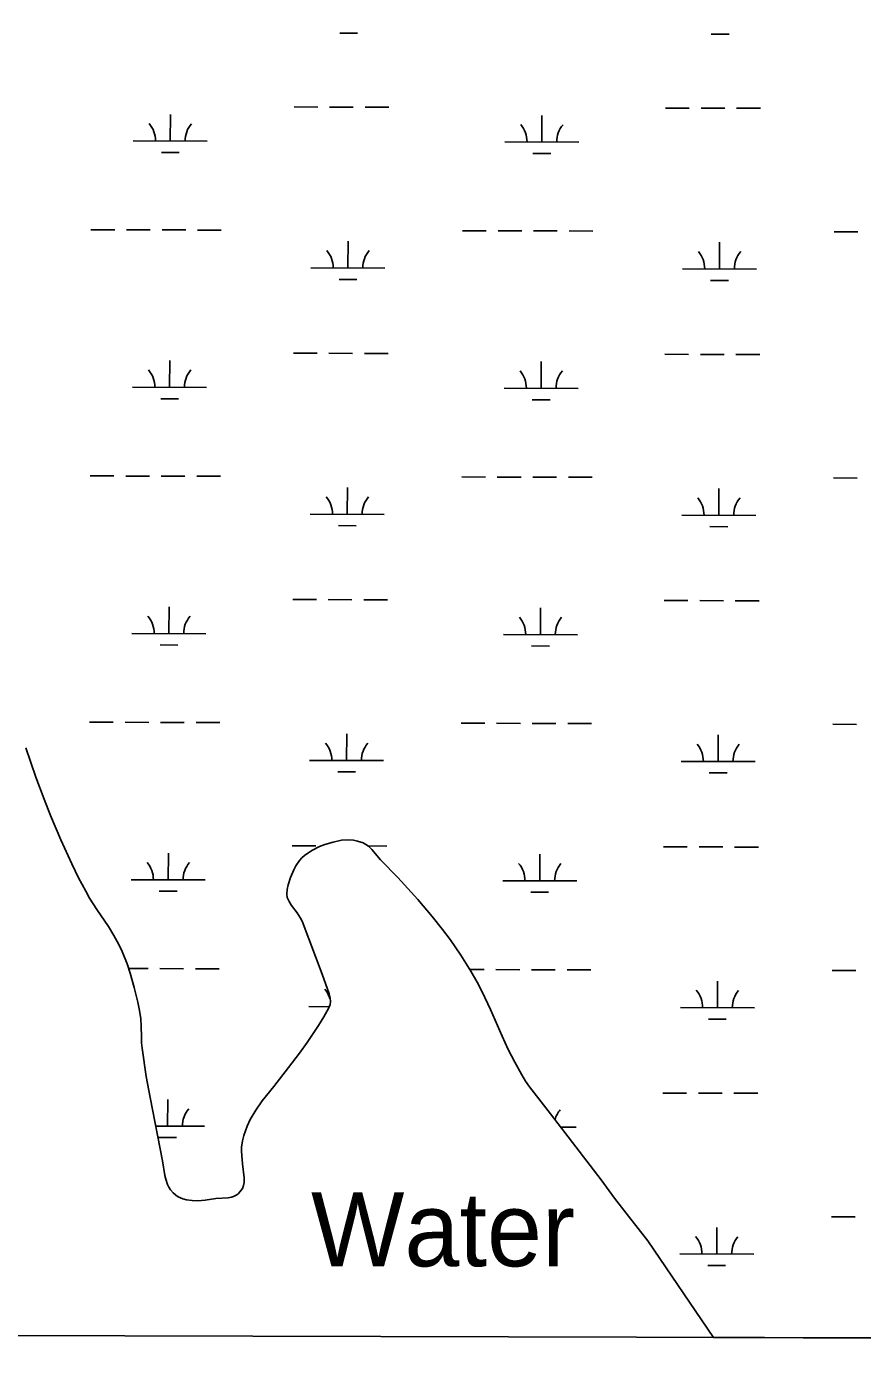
# Model space of a CAD drawing. Extents: x 3161615 to 3199515, y 867541 to 892976.
# Drawn here: x 3184624 to 3185752, y 872921 to 874724 of the extents above; entities that cross this region are included whole.
import ezdxf

# ---------------------------------------------------------------- set-up
doc = ezdxf.new("R2010")
doc.units = 0
for name, color, linetype in [('V-GRID-FRAM', 7, 'Continuous'), ('V-RIVR-IDEN', 7, 'Continuous'), ('V-SITE-VEGE', 7, 'Continuous'), ('V-TOPO-SHOR', 7, 'Continuous'), ('V-WETL-SWMP', 7, 'Continuous')]:
    doc.layers.add(name, color=color, linetype=linetype)

msp = doc.modelspace()

# ---------------------------------------------------------------- linework, layer by layer
at = {"layer": 'V-GRID-FRAM'}
msp.add_lwpolyline([(3165877.4, 891195.5), (3197229, 891108.8), (3197186.7, 872920.9), (3165819.2, 873007.6), (3165877.4, 891195.5)], dxfattribs=at)
at = {"layer": 'V-SITE-VEGE'}
for p, q in [((3184622.6, 873749.8), (3184636.1, 873709.8)), ((3184636.1, 873709.8), (3184647.2, 873680.2)), ((3184647.2, 873680.2), (3184655.9, 873658.1)), ((3184655.9, 873658.1), (3184669.8, 873625.3)), ((3184669.8, 873625.3), (3184684.6, 873592.8)), ((3185009.9, 873611.5), (3185019.2, 873616.2)), ((3185019.2, 873616.2), (3185026.4, 873619)), ((3185026.4, 873619), (3185037.5, 873622.3)), ((3185037.5, 873622.3), (3185048.9, 873624.7)), ((3185048.9, 873624.7), (3185056.9, 873625.5)), ((3185056.9, 873625.5), (3185065, 873624.9)), ((3185065, 873624.9), (3185070.4, 873623.7)), ((3185070.4, 873623.7), (3185078.4, 873621.2)), ((3185078.4, 873621.2), (3185082, 873619.2)), ((3185082, 873619.2), (3185085.3, 873616.6)), ((3185085.3, 873616.6), (3185089.7, 873612.1)), ((3184987.1, 873590.1), (3184992.2, 873597.4)), ((3184992.2, 873597.4), (3184995.3, 873600.8)), ((3184995.3, 873600.8), (3184998.8, 873604)), ((3184998.8, 873604), (3185004.7, 873608.3)), ((3185004.7, 873608.3), (3185009.9, 873611.5)), ((3185089.7, 873612.1), (3185101.5, 873598.3)), ((3185101.5, 873598.3), (3185124.8, 873574.6)), ((3184684.6, 873592.8), (3184693.7, 873574.1)), ((3184980.1, 873574.6), (3184984.3, 873584.7)), ((3184984.3, 873584.7), (3184987.1, 873590.1)), ((3184693.7, 873574.1), (3184703.4, 873555.8)), ((3184975.5, 873558), (3184977, 873564.4)), ((3184977, 873564.4), (3184980.1, 873574.6)), ((3185124.8, 873574.6), (3185151.9, 873544.8)), ((3184703.4, 873555.8), (3184708.6, 873546.6)), ((3184708.6, 873546.6), (3184718.6, 873531.1)), ((3184975, 873551.7), (3184975.5, 873558)), ((3184975.6, 873547.6), (3184975, 873551.7)), ((3184978, 873542), (3184975.6, 873547.6)), ((3184981.2, 873536.7), (3184978, 873542)), ((3185151.9, 873544.8), (3185171.3, 873521.8)), ((3184718.6, 873531.1), (3184734.2, 873508.1)), ((3184989, 873526.6), (3184981.2, 873536.7)), ((3184993.6, 873519.6), (3184989, 873526.6)), ((3184734.2, 873508.1), (3184741.5, 873496.3)), ((3184995.6, 873515.3), (3184993.6, 873519.6)), ((3185022.9, 873443.7), (3184995.6, 873515.3)), ((3185171.3, 873521.8), (3185185.4, 873504.1)), ((3184741.5, 873496.3), (3184748.2, 873484)), ((3185185.4, 873504.1), (3185195.5, 873490.5)), ((3185195.5, 873490.5), (3185210, 873469.6)), ((3184748.2, 873484), (3184752.6, 873474.6)), ((3184752.6, 873474.6), (3184759.2, 873458)), ((3184759.2, 873458), (3184763.4, 873445.2)), ((3185210, 873469.6), (3185223.7, 873448.1)), ((3184763.4, 873445.2), (3184768.9, 873425.8)), ((3185032.4, 873417.5), (3185022.9, 873443.7)), ((3185223.7, 873448.1), (3185232.1, 873433.1)), ((3184768.9, 873425.8), (3184773.7, 873406.2)), ((3185033.8, 873412.1), (3185032.4, 873417.5)), ((3185232.1, 873433.1), (3185238.9, 873419.8)), ((3185238.9, 873419.8), (3185250, 873396)), ((3184773.7, 873406.2), (3184776.1, 873394.9)), ((3185025, 873386.1), (3185031.9, 873398.2)), ((3185031.9, 873398.2), (3185033.6, 873402.8)), ((3185033.6, 873402.8), (3185034.1, 873406.5)), ((3185034.1, 873406.5), (3185033.8, 873412.1)), ((3184776.1, 873394.9), (3184777.8, 873383.5)), ((3184777.8, 873383.5), (3184778.5, 873373.6)), ((3185017.8, 873374.4), (3185025, 873386.1)), ((3185250, 873396), (3185265.9, 873360)), ((3184778.5, 873373.6), (3184778.6, 873358.6)), ((3185002.6, 873351.7), (3185017.8, 873374.4)), ((3184778.6, 873358.6), (3184778.9, 873351.2)), ((3184778.9, 873351.2), (3184779.5, 873343.7)), ((3184779.5, 873343.7), (3184785.2, 873305.6)), ((3184992, 873337), (3185002.6, 873351.7)), ((3185265.9, 873360), (3185274.2, 873342.2)), ((3184977.5, 873317.7), (3184992, 873337)), ((3185274.2, 873342.2), (3185283.2, 873324.8)), ((3184957.7, 873292.2), (3184977.5, 873317.7)), ((3185283.2, 873324.8), (3185292.4, 873307.8)), ((3185292.4, 873307.8), (3185297.3, 873299.5)), ((3184785.2, 873305.6), (3184790.3, 873277.1)), ((3184941.6, 873272.7), (3184957.7, 873292.2)), ((3185297.3, 873299.5), (3185302.8, 873291.5)), ((3185302.8, 873291.5), (3185331.3, 873255.2)), ((3184790.3, 873277.1), (3184807.2, 873191.9)), ((3184933.1, 873260.3), (3184941.6, 873272.7)), ((3184925.7, 873247.3), (3184933.1, 873260.3)), ((3185331.3, 873255.2), (3185399.5, 873166.2)), ((3184917.2, 873225.9), (3184921.5, 873238.3)), ((3184921.5, 873238.3), (3184925.7, 873247.3)), ((3184913.9, 873210.2), (3184915.3, 873218.7)), ((3184915.3, 873218.7), (3184917.2, 873225.9)), ((3184913.7, 873204.6), (3184913.9, 873210.2)), ((3184915.2, 873187.6), (3184913.7, 873204.6)), ((3184807.2, 873191.9), (3184810.3, 873172)), ((3184917.5, 873168.5), (3184915.2, 873187.6)), ((3184810.3, 873172), (3184811.5, 873167)), ((3184811.5, 873167), (3184814, 873159.7)), ((3184917.4, 873162.2), (3184917.5, 873168.5)), ((3185399.5, 873166.2), (3185417.8, 873141.4)), ((3184814, 873159.7), (3184815.8, 873156.1)), ((3184815.8, 873156.1), (3184818, 873152.5)), ((3184818, 873152.5), (3184821.5, 873148.3)), ((3184821.5, 873148.3), (3184824.9, 873145.2)), ((3184824.9, 873145.2), (3184828.3, 873143.1)), ((3184903.2, 873143.5), (3184907.6, 873145.9)), ((3184907.6, 873145.9), (3184909.7, 873147.6)), ((3184909.7, 873147.6), (3184911.8, 873149.7)), ((3184911.8, 873149.7), (3184915, 873154.4)), ((3184915, 873154.4), (3184916.7, 873158.5)), ((3184916.7, 873158.5), (3184917.4, 873162.2)), ((3184828.3, 873143.1), (3184834.6, 873140.3)), ((3184834.6, 873140.3), (3184839.6, 873138.9)), ((3184839.6, 873138.9), (3184847.3, 873137.9)), ((3184847.3, 873137.9), (3184855, 873137.7)), ((3184855, 873137.7), (3184859.8, 873138)), ((3184859.8, 873138), (3184864.6, 873138.5)), ((3184864.6, 873138.5), (3184879, 873140.7)), ((3184879, 873140.7), (3184896, 873141.8)), ((3184896, 873141.8), (3184900.1, 873142.5)), ((3184900.1, 873142.5), (3184903.2, 873143.5)), ((3185417.8, 873141.4), (3185436.4, 873116.8)), ((3185436.4, 873116.8), (3185462.8, 873083.4)), ((3185462.8, 873083.4), (3185551.6, 872953)), ((3185551.6, 872953), (3188886.4, 872943.8))]:
    msp.add_line(p, q, dxfattribs=at)
at = {"layer": 'V-TOPO-SHOR'}
for points in [[(3184622.6, 873749.8), (3184636.1, 873709.8), (3184647.2, 873680.2), (3184655.9, 873658.1), (3184669.8, 873625.3), (3184684.6, 873592.8), (3184693.7, 873574.1), (3184703.4, 873555.8), (3184708.6, 873546.6), (3184718.6, 873531.1), (3184734.2, 873508.1), (3184741.5, 873496.3), (3184748.2, 873484), (3184752.6, 873474.6), (3184759.2, 873458), (3184763.4, 873445.2), (3184768.9, 873425.8), (3184773.7, 873406.2), (3184776.1, 873394.9), (3184777.8, 873383.5), (3184778.5, 873373.6), (3184778.6, 873358.6), (3184778.9, 873351.2), (3184779.5, 873343.7), (3184785.2, 873305.6), (3184790.3, 873277.1), (3184807.2, 873191.9), (3184810.3, 873172), (3184811.5, 873167), (3184814, 873159.7), (3184815.8, 873156.1), (3184818, 873152.5), (3184821.5, 873148.3), (3184824.9, 873145.2), (3184828.3, 873143.1), (3184834.6, 873140.3), (3184839.6, 873138.9), (3184847.3, 873137.9), (3184855, 873137.7), (3184859.8, 873138), (3184864.6, 873138.5), (3184879, 873140.7), (3184896, 873141.8), (3184900.1, 873142.5), (3184903.2, 873143.5), (3184907.6, 873145.9), (3184909.7, 873147.6), (3184911.8, 873149.7), (3184915, 873154.4), (3184916.7, 873158.5), (3184917.4, 873162.2)], [(3184917.4, 873162.2), (3184917.5, 873168.5), (3184915.2, 873187.6), (3184914.2, 873198.9), (3184913.7, 873204.6), (3184913.9, 873210.2), (3184915.3, 873218.7), (3184917.2, 873225.9), (3184921.5, 873238.3), (3184925.7, 873247.3), (3184933.1, 873260.3), (3184941.6, 873272.7), (3184957.7, 873292.2), (3184977.5, 873317.7), (3184992, 873337), (3185002.6, 873351.7), (3185017.8, 873374.4), (3185025, 873386.1), (3185031.9, 873398.2), (3185033.6, 873402.8), (3185034.1, 873406.5), (3185033.8, 873412.1), (3185032.4, 873417.5), (3185022.9, 873443.7), (3184995.6, 873515.3), (3184993.6, 873519.6), (3184989, 873526.6), (3184981.2, 873536.7), (3184978, 873542), (3184975.6, 873547.6), (3184975, 873551.7), (3184975.5, 873558), (3184977, 873564.4), (3184980.1, 873574.6), (3184984.3, 873584.7), (3184987.1, 873590.1), (3184992.2, 873597.4), (3184995.3, 873600.8), (3184998.8, 873604), (3185004.7, 873608.3), (3185009.9, 873611.5), (3185019.2, 873616.2), (3185026.4, 873619), (3185037.5, 873622.3), (3185048.9, 873624.7), (3185056.9, 873625.5), (3185065, 873624.9), (3185070.4, 873623.7), (3185078.4, 873621.2), (3185082, 873619.2), (3185085.3, 873616.6), (3185089.7, 873612.1), (3185101.5, 873598.3), (3185124.8, 873574.6), (3185151.9, 873544.8), (3185171.3, 873521.8), (3185185.4, 873504.1), (3185195.5, 873490.5), (3185210, 873469.6), (3185223.7, 873448.1), (3185232.1, 873433.1), (3185238.9, 873419.8), (3185250, 873396), (3185265.9, 873360), (3185274.2, 873342.2), (3185283.2, 873324.8), (3185292.4, 873307.8), (3185297.3, 873299.5), (3185302.8, 873291.5), (3185331.3, 873255.2), (3185399.5, 873166.2), (3185417.8, 873141.4), (3185436.4, 873116.8), (3185462.8, 873083.4)], [(3185462.8, 873083.4), (3185551.6, 872953)]]:
    msp.add_lwpolyline(points, dxfattribs=at)
at = {"layer": 'V-WETL-SWMP'}
for p, q in [((3185046.5, 874715.1), (3185070.5, 874715.1)), ((3185548.4, 874713.7), (3185572.4, 874713.7)), ((3184984.8, 874615.3), (3185016.8, 874615.2)), ((3185032.8, 874615.2), (3185064.8, 874615.1)), ((3185080.8, 874615), (3185112.8, 874614.9)), ((3185486.7, 874613.9), (3185518.7, 874613.8)), ((3185534.7, 874613.8), (3185566.7, 874613.7)), ((3185582.7, 874613.6), (3185614.7, 874613.5)), ((3184817.6, 874569.3), (3184817.7, 874605.3)), ((3185319.5, 874567.9), (3185319.6, 874603.9)), ((3184767.6, 874569.5), (3184867.6, 874569.2)), ((3184805.6, 874553.9), (3184829.6, 874553.9)), ((3185269.5, 874568.1), (3185369.5, 874567.8)), ((3185307.5, 874552.5), (3185331.5, 874552.5)), ((3184710.5, 874449.5), (3184742.5, 874449.5)), ((3184758.5, 874449.4), (3184790.5, 874449.3)), ((3184806.5, 874449.3), (3184838.5, 874449.2)), ((3184854.5, 874449.1), (3184886.5, 874449.1)), ((3185212.4, 874448.2), (3185244.4, 874448.1)), ((3185260.4, 874448), (3185292.4, 874447.9)), ((3185308.4, 874447.9), (3185340.4, 874447.8)), ((3185356.4, 874447.8), (3185388.4, 874447.7)), ((3185714.3, 874446.8), (3185746.3, 874446.7)), ((3185057.6, 874397.8), (3185057.7, 874433.8)), ((3185559.5, 874396.5), (3185559.6, 874432.5)), ((3185007.6, 874398), (3185107.6, 874397.7)), ((3185509.5, 874396.6), (3185609.5, 874396.3)), ((3185045.6, 874382.4), (3185069.6, 874382.4)), ((3185547.5, 874381.1), (3185571.5, 874381)), ((3184983.9, 874282.6), (3185015.9, 874282.5)), ((3185031.9, 874282.5), (3185063.9, 874282.4)), ((3185079.9, 874282.4), (3185111.9, 874282.3)), ((3185485.8, 874281.2), (3185517.8, 874281.1)), ((3185533.8, 874281.1), (3185565.8, 874281)), ((3185581.8, 874281), (3185613.8, 874280.9)), ((3184816.7, 874236.6), (3184816.8, 874272.6)), ((3185318.6, 874235.3), (3185318.7, 874271.3)), ((3184766.7, 874236.8), (3184866.7, 874236.5)), ((3185268.6, 874235.4), (3185368.6, 874235.1)), ((3184804.7, 874221.2), (3184828.7, 874221.2)), ((3185306.6, 874219.9), (3185330.6, 874219.8)), ((3184709.5, 874116.9), (3184741.5, 874116.8)), ((3184757.5, 874116.7), (3184789.5, 874116.7)), ((3184805.5, 874116.6), (3184837.5, 874116.5)), ((3184853.5, 874116.5), (3184885.5, 874116.4)), ((3185056.7, 874065.2), (3185056.8, 874101.2)), ((3185211.4, 874115.5), (3185243.4, 874115.4)), ((3185259.4, 874115.4), (3185291.4, 874115.3)), ((3185307.4, 874115.2), (3185339.4, 874115.1)), ((3185355.4, 874115.1), (3185387.4, 874115)), ((3185713.4, 874114.1), (3185745.4, 874114)), ((3185558.6, 874063.8), (3185558.7, 874099.8)), ((3185006.7, 874065.3), (3185106.7, 874065)), ((3185044.7, 874049.8), (3185068.7, 874049.7)), ((3185508.6, 874063.9), (3185608.6, 874063.6)), ((3185546.6, 874048.4), (3185570.6, 874048.3)), ((3184815.8, 873904), (3184815.9, 873940)), ((3184983, 873949.9), (3185015, 873949.9)), ((3185031, 873949.8), (3185063, 873949.7)), ((3185079, 873949.7), (3185111, 873949.6)), ((3185317.7, 873902.6), (3185317.8, 873938.6)), ((3185484.9, 873948.6), (3185516.9, 873948.5)), ((3185532.9, 873948.4), (3185564.9, 873948.3)), ((3185580.9, 873948.3), (3185612.9, 873948.2)), ((3184765.8, 873904.1), (3184865.8, 873903.8)), ((3185267.7, 873902.7), (3185367.7, 873902.4)), ((3184803.8, 873888.6), (3184827.8, 873888.5)), ((3185305.7, 873887.2), (3185329.7, 873887.1)), ((3184708.6, 873784.2), (3184740.6, 873784.1)), ((3184756.6, 873784.1), (3184788.6, 873784)), ((3184804.6, 873783.9), (3184836.6, 873783.8)), ((3184852.6, 873783.8), (3184884.6, 873783.7)), ((3185210.5, 873782.8), (3185242.5, 873782.7)), ((3185258.5, 873782.7), (3185290.5, 873782.6)), ((3185306.5, 873782.5), (3185338.5, 873782.5)), ((3185354.5, 873782.4), (3185386.5, 873782.3)), ((3185712.4, 873781.4), (3185744.4, 873781.3)), ((3185055.8, 873732.5), (3185055.9, 873768.5)), ((3185557.7, 873731.1), (3185557.8, 873767.1)), ((3184622.6, 873749.8), (3184636.1, 873709.8)), ((3185005.8, 873732.6), (3185105.8, 873732.4)), ((3185507.7, 873731.2), (3185607.7, 873731)), ((3184636.1, 873709.8), (3184647.2, 873680.2)), ((3185043.8, 873717.1), (3185067.8, 873717)), ((3185545.7, 873715.7), (3185569.7, 873715.6)), ((3184647.2, 873680.2), (3184655.9, 873658.1)), ((3184655.9, 873658.1), (3184669.8, 873625.3)), ((3184669.8, 873625.3), (3184684.6, 873592.8)), ((3184982.1, 873617.3), (3185014.1, 873617.2)), ((3185009.9, 873611.5), (3185019.2, 873616.2)), ((3185019.2, 873616.2), (3185026.4, 873619)), ((3185026.4, 873619), (3185037.5, 873622.3)), ((3185037.5, 873622.3), (3185048.9, 873624.7)), ((3185048.9, 873624.7), (3185056.9, 873625.5)), ((3185056.9, 873625.5), (3185065, 873624.9)), ((3185065, 873624.9), (3185070.4, 873623.7)), ((3185070.4, 873623.7), (3185078.4, 873621.2)), ((3185078.4, 873621.2), (3185082, 873619.2)), ((3185082, 873619.2), (3185085.3, 873616.6)), ((3185084.9, 873617), (3185110.1, 873616.9)), ((3185085.3, 873616.6), (3185089.7, 873612.1)), ((3185484, 873615.9), (3185516, 873615.8)), ((3185532, 873615.7), (3185564, 873615.7)), ((3185580, 873615.6), (3185612, 873615.5)), ((3184814.9, 873571.3), (3184815, 873607.3)), ((3184987.1, 873590.1), (3184992.2, 873597.4)), ((3184992.2, 873597.4), (3184995.3, 873600.8)), ((3184995.3, 873600.8), (3184998.8, 873604)), ((3184998.8, 873604), (3185004.7, 873608.3)), ((3185004.7, 873608.3), (3185009.9, 873611.5)), ((3185089.7, 873612.1), (3185101.5, 873598.3)), ((3185101.5, 873598.3), (3185124.8, 873574.6)), ((3185316.8, 873569.9), (3185316.9, 873605.9)), ((3184684.6, 873592.8), (3184693.7, 873574.1)), ((3184980.1, 873574.6), (3184984.3, 873584.7)), ((3184984.3, 873584.7), (3184987.1, 873590.1)), ((3184693.7, 873574.1), (3184703.4, 873555.8)), ((3184764.9, 873571.4), (3184864.9, 873571.2)), ((3184975.5, 873558), (3184977, 873564.4)), ((3184977, 873564.4), (3184980.1, 873574.6)), ((3185124.8, 873574.6), (3185151.9, 873544.8)), ((3185266.8, 873570.1), (3185366.8, 873569.8)), ((3184703.4, 873555.8), (3184708.6, 873546.6)), ((3184708.6, 873546.6), (3184718.6, 873531.1)), ((3184802.8, 873555.9), (3184826.8, 873555.8)), ((3184975, 873551.7), (3184975.5, 873558)), ((3184975.6, 873547.6), (3184975, 873551.7)), ((3184978, 873542), (3184975.6, 873547.6)), ((3184981.2, 873536.7), (3184978, 873542)), ((3185151.9, 873544.8), (3185171.3, 873521.8)), ((3185304.7, 873554.5), (3185328.7, 873554.4)), ((3184718.6, 873531.1), (3184734.2, 873508.1)), ((3184989, 873526.6), (3184981.2, 873536.7)), ((3184993.6, 873519.6), (3184989, 873526.6)), ((3184734.2, 873508.1), (3184741.5, 873496.3)), ((3184995.6, 873515.3), (3184993.6, 873519.6)), ((3185022.9, 873443.7), (3184995.6, 873515.3)), ((3185171.3, 873521.8), (3185185.4, 873504.1)), ((3184741.5, 873496.3), (3184748.2, 873484)), ((3185185.4, 873504.1), (3185195.5, 873490.5)), ((3185195.5, 873490.5), (3185210, 873469.6)), ((3184748.2, 873484), (3184752.6, 873474.6)), ((3184752.6, 873474.6), (3184759.2, 873458)), ((3184759.2, 873458), (3184763.4, 873445.2)), ((3185210, 873469.6), (3185223.7, 873448.1)), ((3184761.4, 873451.4), (3184787.7, 873451.3)), ((3184763.4, 873445.2), (3184768.9, 873425.8)), ((3184803.7, 873451.3), (3184835.7, 873451.2)), ((3184851.7, 873451.1), (3184883.7, 873451)), ((3185032.4, 873417.5), (3185022.9, 873443.7)), ((3185222.4, 873450.1), (3185241.6, 873450)), ((3185223.7, 873448.1), (3185232.1, 873433.1)), ((3185257.6, 873450), (3185289.6, 873449.9)), ((3185305.6, 873449.9), (3185337.6, 873449.8)), ((3185353.6, 873449.7), (3185385.6, 873449.7)), ((3185556.8, 873398.4), (3185556.9, 873434.4)), ((3185711.5, 873448.8), (3185743.5, 873448.7)), ((3184768.9, 873425.8), (3184773.7, 873406.2)), ((3185033.8, 873412.1), (3185032.4, 873417.5)), ((3185232.1, 873433.1), (3185238.9, 873419.8)), ((3185238.9, 873419.8), (3185250, 873396)), ((3184773.7, 873406.2), (3184776.1, 873394.9)), ((3185004.9, 873400), (3185032.5, 873399.9)), ((3185025, 873386.1), (3185031.9, 873398.2)), ((3185031.9, 873398.2), (3185033.6, 873402.8)), ((3185033.6, 873402.8), (3185034.1, 873406.5)), ((3185034.1, 873406.5), (3185033.8, 873412.1)), ((3185506.8, 873398.6), (3185606.8, 873398.3)), ((3184776.1, 873394.9), (3184777.8, 873383.5)), ((3184777.8, 873383.5), (3184778.5, 873373.6)), ((3185017.8, 873374.4), (3185025, 873386.1)), ((3185250, 873396), (3185265.9, 873360)), ((3185544.7, 873383), (3185568.7, 873383)), ((3184778.5, 873373.6), (3184778.6, 873358.6)), ((3185002.6, 873351.7), (3185017.8, 873374.4)), ((3184778.6, 873358.6), (3184778.9, 873351.2)), ((3184778.9, 873351.2), (3184779.5, 873343.7)), ((3184779.5, 873343.7), (3184785.2, 873305.6)), ((3184992, 873337), (3185002.6, 873351.7)), ((3185265.9, 873360), (3185274.2, 873342.2)), ((3184977.5, 873317.7), (3184992, 873337)), ((3185274.2, 873342.2), (3185283.2, 873324.8)), ((3184957.7, 873292.2), (3184977.5, 873317.7)), ((3185283.2, 873324.8), (3185292.4, 873307.8)), ((3185292.4, 873307.8), (3185297.3, 873299.5)), ((3184785.2, 873305.6), (3184790.3, 873277.1)), ((3184941.6, 873272.7), (3184957.7, 873292.2)), ((3185297.3, 873299.5), (3185302.8, 873291.5)), ((3185302.8, 873291.5), (3185331.3, 873255.2)), ((3184790.3, 873277.1), (3184807.2, 873191.9)), ((3184814, 873238.6), (3184814.1, 873274.6)), ((3184933.1, 873260.3), (3184941.6, 873272.7)), ((3185483.1, 873283.2), (3185515.1, 873283.1)), ((3185531.1, 873283.1), (3185563.1, 873283)), ((3185579.1, 873282.9), (3185611.1, 873282.9)), ((3184925.7, 873247.3), (3184933.1, 873260.3)), ((3185331.3, 873255.2), (3185399.5, 873166.2)), ((3184797.9, 873238.7), (3184864, 873238.5)), ((3184917.2, 873225.9), (3184921.5, 873238.3)), ((3184921.5, 873238.3), (3184925.7, 873247.3)), ((3185345.1, 873237.2), (3185365.9, 873237.1)), ((3184801.9, 873223.2), (3184825.9, 873223.2)), ((3184913.9, 873210.2), (3184915.3, 873218.7)), ((3184915.3, 873218.7), (3184917.2, 873225.9)), ((3184913.7, 873204.6), (3184913.9, 873210.2)), ((3184914.2, 873198.9), (3184913.7, 873204.6)), ((3184807.2, 873191.9), (3184810.3, 873172)), ((3184915.2, 873187.6), (3184914.2, 873198.9)), ((3184917.5, 873168.5), (3184915.2, 873187.6)), ((3184810.3, 873172), (3184811.5, 873167)), ((3184811.5, 873167), (3184814, 873159.7)), ((3184917.4, 873162.2), (3184917.5, 873168.5)), ((3185399.5, 873166.2), (3185417.8, 873141.4)), ((3184814, 873159.7), (3184815.8, 873156.1)), ((3184815.8, 873156.1), (3184818, 873152.5)), ((3184818, 873152.5), (3184821.5, 873148.3)), ((3184821.5, 873148.3), (3184824.9, 873145.2)), ((3184824.9, 873145.2), (3184828.3, 873143.1)), ((3184903.2, 873143.5), (3184907.6, 873145.9)), ((3184907.6, 873145.9), (3184909.7, 873147.6)), ((3184909.7, 873147.6), (3184911.8, 873149.7)), ((3184911.8, 873149.7), (3184915, 873154.4)), ((3184915, 873154.4), (3184916.7, 873158.5)), ((3184916.7, 873158.5), (3184917.4, 873162.2)), ((3184828.3, 873143.1), (3184834.6, 873140.3)), ((3184834.6, 873140.3), (3184839.6, 873138.9)), ((3184839.6, 873138.9), (3184847.3, 873137.9)), ((3184847.3, 873137.9), (3184855, 873137.7)), ((3184855, 873137.7), (3184859.8, 873138)), ((3184859.8, 873138), (3184864.6, 873138.5)), ((3184864.6, 873138.5), (3184879, 873140.7)), ((3184879, 873140.7), (3184896, 873141.8)), ((3184896, 873141.8), (3184900.1, 873142.5)), ((3184900.1, 873142.5), (3184903.2, 873143.5)), ((3185417.8, 873141.4), (3185436.4, 873116.8)), ((3185436.4, 873116.8), (3185462.8, 873083.4)), ((3185710.6, 873116.1), (3185742.6, 873116)), ((3185555.9, 873065.8), (3185556, 873101.8)), ((3185462.8, 873083.4), (3185551.6, 872953)), ((3185505.9, 873065.9), (3185605.9, 873065.6)), ((3185543.8, 873050.4), (3185567.8, 873050.3)), ((3185551.6, 872953), (3186556.9, 872950.3))]:
    msp.add_line(p, q, dxfattribs=at)
for centre, start, end in [((3184762.4, 874569.9), 359.0699, 40.6135), ((3184872.9, 874569.6), 139.0699, 180.6135), ((3185264.3, 874568.6), 359.0699, 40.6135), ((3185374.8, 874568.3), 139.0699, 180.6135), ((3185002.4, 874398.5), 359.0699, 40.6135), ((3185112.9, 874398.2), 139.0699, 180.6135), ((3185504.3, 874397.1), 359.0699, 40.6135), ((3185614.8, 874396.8), 139.0699, 180.6135), ((3184761.5, 874237.3), 359.0699, 40.6135), ((3184872, 874237), 139.0699, 180.6135), ((3185263.4, 874235.9), 359.0699, 40.6135), ((3185373.9, 874235.6), 139.0699, 180.6135), ((3185001.5, 874065.8), 359.0699, 40.6135), ((3185112, 874065.5), 139.0699, 180.6135), ((3185503.4, 874064.4), 359.0699, 40.6135), ((3185613.9, 874064.1), 139.0699, 180.6135), ((3184760.6, 873904.6), 359.0699, 40.6135), ((3184871, 873904.3), 139.0699, 180.6135), ((3185262.5, 873903.2), 359.0699, 40.6135), ((3185372.9, 873902.9), 139.0699, 180.6135), ((3185000.6, 873733.1), 359.0699, 40.6135), ((3185111, 873732.8), 139.0699, 180.6135), ((3185502.5, 873731.7), 359.0699, 40.6135), ((3185612.9, 873731.4), 139.0699, 180.6135), ((3184759.6, 873571.9), 359.0699, 40.6135), ((3184870.1, 873571.6), 139.0699, 180.6135), ((3185261.5, 873570.5), 359.0699, 40.6135), ((3185372, 873570.2), 139.0699, 180.6135), ((3184999.6, 873400.5), 12.6502, 40.6135), ((3185501.5, 873399.1), 359.0699, 40.6135), ((3185612, 873398.8), 139.0699, 180.6135), ((3184869.2, 873238.9), 139.0699, 180.6135), ((3185371.1, 873237.6), 139.0699, 163.7838), ((3185500.6, 873066.4), 359.0699, 40.6135), ((3185611.1, 873066.1), 139.0699, 180.6135)]:
    msp.add_arc(centre, 35.2, start, end, dxfattribs=at)

# ---------------------------------------------------------------- texts
at = {"layer": 'V-RIVR-IDEN'}
msp.add_text('Water', height=100, dxfattribs=at).set_placement((3185007.7, 873049.2))

doc.saveas('drawing.dxf')
